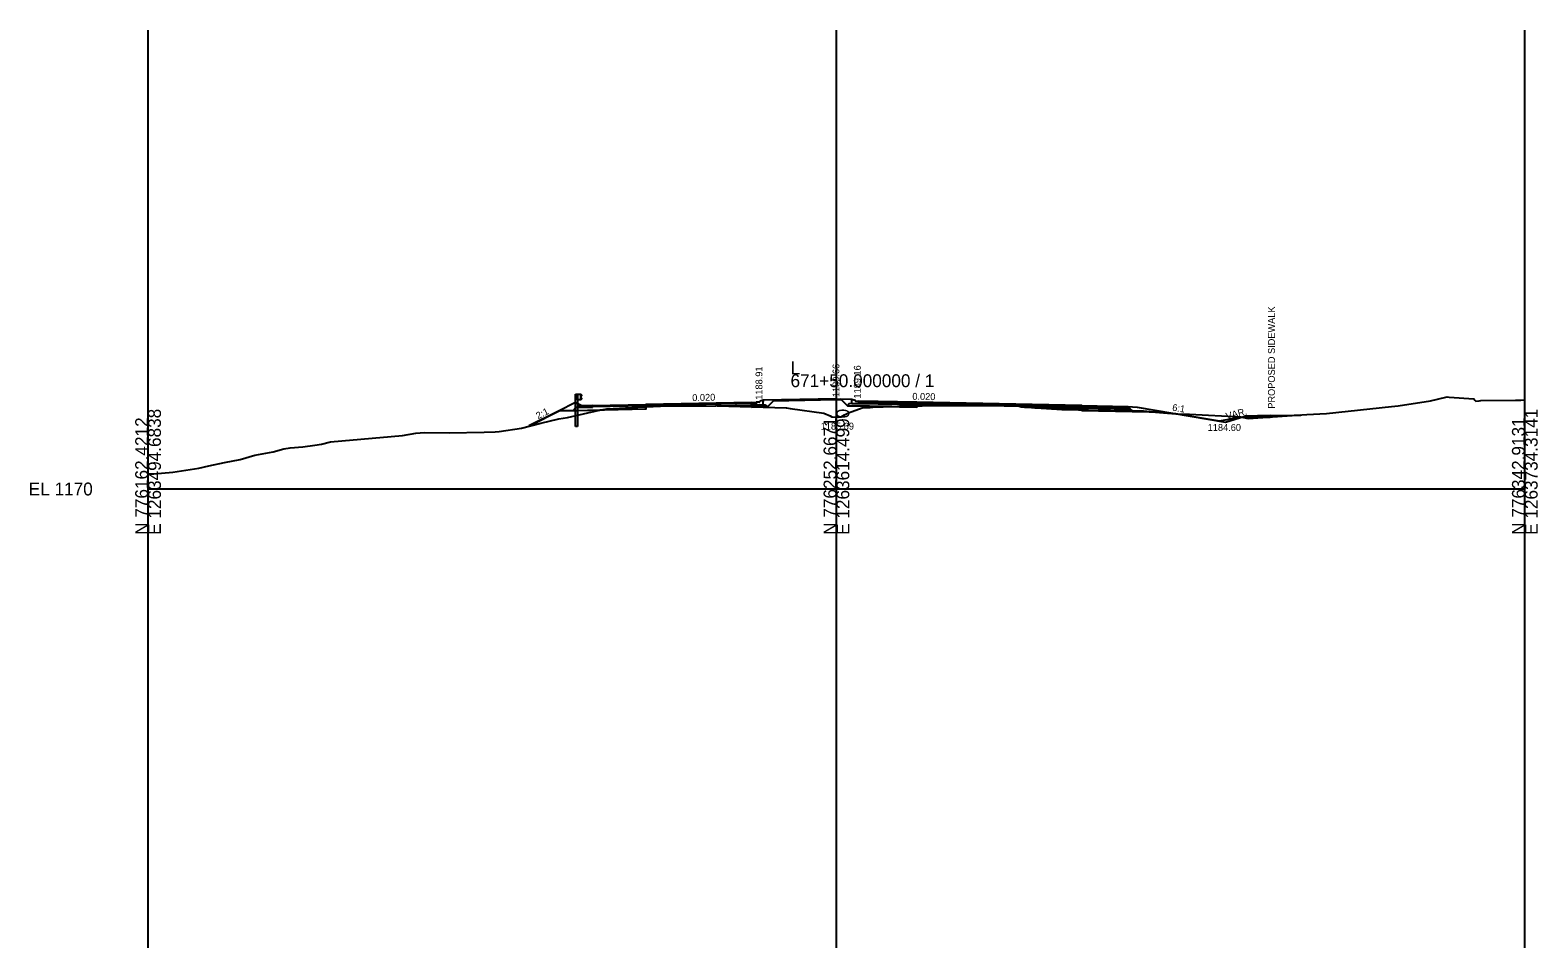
# Model space of a CAD drawing. Extents: x -41 to 1262860, y -100 to 777489.
# Drawn here: x -25.7 to 302.8, y 4085 to 4285 of the extents above; entities that cross this region are included whole.
import ezdxf

# ---------------------------------------------------------------- set-up
doc = ezdxf.new("R2010")
doc.units = 0
for name, color, linetype in [('Exist Cross Section Cell', 7, 'Continuous'), ('Exist XS Center Line Elevation Label', 7, 'Continuous'), ('Exist XS Ground Line', 7, 'Continuous'), ('Prop CMT Guardrail Graphics', 7, 'Continuous'), ('Prop CMT Pvmt Concrete', 7, 'Continuous'), ('Prop CMT Pvmt Course 1', 7, 'Continuous'), ('Prop CMT Pvmt Course 4', 7, 'Continuous'), ('Prop CMT Pvmt Surface', 7, 'Continuous'), ('Prop CMT Shld Paved Course 1', 7, 'Continuous'), ('Prop CMT Shld Paved Course 2', 7, 'Continuous'), ('Prop CMT Shld Paved Course 4', 7, 'Continuous'), ('Prop CMT Slope Grass', 7, 'Continuous'), ('Prop CMT Subgrade Earthwork', 7, 'Continuous'), ('Prop Conc Curb and Gutter', 7, 'Continuous'), ('Prop Conc Island Cover', 7, 'Continuous'), ('Prop XS Ditch Standard Text', 7, 'Continuous'), ('Prop XS Earthwork Shape', 7, 'Continuous'), ('Prop XS Elevation Labels', 7, 'Continuous'), ('Prop XS Exc Vertical Line 1', 7, 'Continuous'), ('Prop XS Exc Vertical Line 2', 7, 'Continuous'), ('Prop XS Exc Vertical Line 3', 7, 'Continuous'), ('Prop XS Finish Grade', 7, 'Continuous'), ('Prop XS Hydro Elevations', 7, 'Continuous'), ('Prop XS SE Text', 7, 'Continuous'), ('Prop XS Side Slope Text', 7, 'Continuous'), ('Scratch_Level_0', 7, 'Continuous'), ('Scratch_Level_1', 7, 'Continuous'), ('Scratch_Level_4', 7, 'Continuous'), ('Scratch_Level_6', 7, 'Continuous'), ('Typical Curb CELL', 7, 'Continuous')]:
    doc.layers.add(name, color=color, linetype=linetype)

msp = doc.modelspace()

# ---------------------------------------------------------------- linework, layer by layer
at = {"layer": 'Exist Cross Section Cell'}
for p, q in [((150, 4185), (150, 4210)), ((0, 4185), (150, 4185)), ((150, 4185), (300, 4185))]:
    msp.add_line(p, q, dxfattribs=at)
at = {"layer": 'Exist XS Ground Line'}
msp.add_lwpolyline([(0, 4188.19), (1.25, 4188.27), (5.42, 4188.68), (11.06, 4189.57), (13.24, 4190.03), (16.64, 4190.74), (20.1, 4191.4), (23.26, 4192.34), (27.27, 4193.11), (29.58, 4193.74), (30.93, 4193.95), (33.75, 4194.16), (36.34, 4194.53), (37.8, 4194.78), (39.72, 4195.25), (55.47, 4196.67), (58.32, 4197.15), (60.24, 4197.34), (65.58, 4197.24), (73.27, 4197.41), (75.61, 4197.46), (76.49, 4197.5), (81.36, 4198.29), (85.61, 4199.38), (89.52, 4200.26), (91.43, 4200.58), (98.34, 4202.15), (99.94, 4202.49), (102.73, 4202.62), (108, 4202.88), (108.47, 4202.9), (111.69, 4203.03), (123.74, 4203.16), (124.01, 4203.17), (124.04, 4203.16), (136.61, 4202.79), (139.05, 4202.67), (139.15, 4202.66), (139.9, 4202.56), (147.26, 4201.53), (148.6, 4200.91), (148.97, 4200.73), (150.46, 4200.68), (151.03, 4200.71), (151.77, 4201.19), (152.37, 4201.48), (152.63, 4201.61), (152.66, 4201.61), (155.62, 4202.66), (157.34, 4202.76), (157.93, 4202.8), (160.15, 4202.89), (165.51, 4203.1), (168.68, 4203.14), (177.04, 4203.22), (183.2, 4203.19), (189.79, 4203.03), (190.23, 4202.89), (192.49, 4202.74), (193.2, 4202.69), (194.62, 4202.62), (199.11, 4202.31), (200.56, 4202.3), (204.93, 4202.18), (214.62, 4202.07), (216.89, 4201.95), (221.25, 4201.61), (224.82, 4201.34), (226.93, 4201.29), (238.02, 4200.7), (239.72, 4200.34), (248.22, 4200.94), (252.49, 4201.2), (256.76, 4201.47), (270.96, 4202.98), (272.41, 4203.14), (279.43, 4204.22), (282.8, 4204.99), (283.1, 4205.06), (283.5, 4205.03), (288.86, 4204.62), (289.11, 4204.37), (289.36, 4204.12), (290.06, 4204.22), (290.44, 4204.27), (297.95, 4204.34), (299.11, 4204.37), (300, 4204.4)], dxfattribs=at)
at = {"layer": 'Prop CMT Guardrail Graphics'}
for p, q in [((93.11, 4205.64), (93.59, 4205.64)), ((93.11, 4203.14), (93.11, 4205.64)), ((93.59, 4204.46), (93.59, 4205.64)), ((93.59, 4205.64), (94.26, 4205.64)), ((93.59, 4205.64), (93.59, 4203.13)), ((94.26, 4205.64), (94.26, 4204.46)), ((94.26, 4205.56), (94.26, 4204.54)), ((94.36, 4205.54), (94.26, 4205.56)), ((94.27, 4205.1), (94.5, 4205.3)), ((94.5, 4205.44), (94.36, 4205.54)), ((94.5, 4205.3), (94.5, 4205.44)), ((93.11, 4198.64), (93.11, 4203.14)), ((94.26, 4204.46), (93.59, 4204.46)), ((93.59, 4203.13), (93.59, 4198.64)), ((94.26, 4204.54), (94.36, 4204.56)), ((94.27, 4205.01), (94.27, 4205.1)), ((94.5, 4204.81), (94.27, 4205.01)), ((94.36, 4204.56), (94.5, 4204.66)), ((94.5, 4204.66), (94.5, 4204.81)), ((93.59, 4198.64), (93.11, 4198.64))]:
    msp.add_line(p, q, dxfattribs=at)
at = {"layer": 'Prop CMT Pvmt Concrete'}
for p, q in [((239.5, 4200.89), (244.5, 4200.99)), ((239.5, 4200.89), (239.5, 4200.55)), ((239.5, 4200.55), (244.51, 4200.65)), ((244.5, 4200.99), (244.5, 4200.65))]:
    msp.add_line(p, q, dxfattribs=at)
at = {"layer": 'Prop CMT Pvmt Course 1'}
for p, q in [((131.5, 4203.62), (132.5, 4203.64)), ((132.5, 4203.64), (132.5, 4203.89)), ((154.86, 4204.15), (154.86, 4203.9)), ((167.5, 4203.64), (154.86, 4203.9))]:
    msp.add_line(p, q, dxfattribs=at)
for points in [[(108.5, 4203.16), (108.5, 4203.41), (108.5, 4203.41), (131.5, 4203.87), (131.5, 4203.62), (131.5, 4203.62), (108.5, 4203.16), (108.5, 4203.16), (108.5, 4203.16)], [(203.5, 4202.92), (203.5, 4203.17), (203.5, 4203.17), (167.5, 4203.89), (167.5, 4203.64), (167.5, 4203.64), (203.5, 4202.92), (203.5, 4202.92), (203.5, 4202.92)]]:
    msp.add_lwpolyline(points, dxfattribs=at)
at = {"layer": 'Prop CMT Pvmt Course 4'}
msp.add_line((108.5, 4202.37), (93.44, 4202.07), dxfattribs=at)
at = {"layer": 'Prop CMT Pvmt Surface'}
for p, q in [((96.82, 4203.18), (108.5, 4203.41)), ((131.5, 4203.87), (108.5, 4203.41)), ((131.5, 4203.87), (132.5, 4203.89)), ((167.5, 4203.89), (154.86, 4204.15)), ((203.5, 4203.17), (167.5, 4203.89)), ((203.5, 4203.17), (213.5, 4202.97))]:
    msp.add_line(p, q, dxfattribs=at)
at = {"layer": 'Prop CMT Shld Paved Course 1'}
for p, q in [((108.5, 4203.16), (96.82, 4202.93)), ((104.5, 4203.33), (104.5, 4203.33)), ((108.5, 4203.41), (108.5, 4203.16)), ((108.5, 4203.16), (108.5, 4203.16)), ((203.5, 4203.17), (203.5, 4202.92)), ((203.5, 4202.92), (203.5, 4202.92)), ((203.5, 4202.92), (213.76, 4202.72)), ((207.5, 4203.09), (207.5, 4203.09)), ((213.76, 4202.72), (213.5, 4202.97))]:
    msp.add_line(p, q, dxfattribs=at)
at = {"layer": 'Prop CMT Shld Paved Course 2'}
for p, q in [((103.9, 4202.74), (103.9, 4202.74)), ((103.9, 4202.74), (103.9, 4202.74)), ((103.9, 4202.74), (103.9, 4202.74)), ((103.9, 4202.74), (103.9, 4202.74)), ((111.69, 4203.23), (108.5, 4203.16)), ((108.5, 4203.16), (108.5, 4202.83)), ((108.5, 4203.16), (108.5, 4203.16)), ((108.5, 4203.16), (108.5, 4202.9)), ((108.5, 4202.9), (111.69, 4203.03)), ((108.5, 4202.9), (108.5, 4202.9)), ((108.5, 4202.9), (108.5, 4202.9)), ((108.5, 4202.83), (108.5, 4202.83)), ((123.74, 4203.47), (111.69, 4203.23)), ((111.69, 4203.23), (111.69, 4203.23)), ((111.69, 4203.23), (111.69, 4203.23)), ((111.69, 4203.03), (123.74, 4203.16)), ((111.69, 4203.03), (111.69, 4203.03)), ((111.69, 4203.03), (111.69, 4203.03)), ((124.01, 4203.47), (123.74, 4203.47)), ((123.74, 4203.47), (123.74, 4203.47)), ((123.74, 4203.16), (124.01, 4203.17)), ((123.74, 4203.16), (123.74, 4203.16)), ((124.04, 4203.47), (124.01, 4203.47)), ((124.01, 4203.17), (124.04, 4203.16)), ((131.5, 4203.62), (124.04, 4203.47)), ((124.04, 4203.47), (124.04, 4203.47)), ((124.04, 4203.16), (124.52, 4203.15)), ((124.52, 4203.15), (131.5, 4203.29)), ((124.52, 4203.15), (124.52, 4203.15)), ((124.52, 4203.15), (124.52, 4203.15)), ((131.5, 4203.29), (131.5, 4203.62)), ((131.5, 4203.62), (131.5, 4203.62)), ((131.5, 4203.29), (132.5, 4203.31)), ((131.5, 4203.29), (131.5, 4203.29)), ((131.5, 4203.29), (131.5, 4203.29)), ((132.5, 4203.64), (132.5, 4203.31)), ((154.86, 4203.56), (154.86, 4203.9)), ((167.5, 4203.31), (154.86, 4203.56)), ((168.68, 4203.62), (167.5, 4203.64)), ((167.5, 4203.64), (167.5, 4203.31)), ((167.5, 4203.31), (167.5, 4203.31)), ((167.5, 4203.31), (168.68, 4203.29)), ((177.04, 4203.45), (168.68, 4203.62)), ((168.68, 4203.62), (168.68, 4203.62)), ((168.68, 4203.29), (168.68, 4203.29)), ((168.68, 4203.29), (173.63, 4203.19)), ((173.63, 4203.19), (177.04, 4203.22)), ((173.63, 4203.19), (173.63, 4203.19)), ((173.63, 4203.19), (173.63, 4203.19)), ((183.2, 4203.33), (177.04, 4203.45)), ((177.04, 4203.45), (177.04, 4203.45)), ((177.04, 4203.22), (183.2, 4203.19)), ((189.79, 4203.2), (183.2, 4203.33)), ((183.2, 4203.33), (183.2, 4203.33)), ((183.2, 4203.19), (183.2, 4203.19)), ((183.2, 4203.19), (189.79, 4203.03)), ((190.23, 4203.19), (189.79, 4203.2)), ((189.79, 4203.2), (189.79, 4203.2)), ((189.79, 4203.2), (189.79, 4203.2)), ((189.79, 4203.2), (189.79, 4203.2)), ((189.79, 4203.03), (189.79, 4203.03)), ((189.79, 4203.03), (189.79, 4203.03)), ((189.79, 4203.03), (189.79, 4203.03)), ((189.79, 4203.03), (190.23, 4202.89)), ((192.49, 4203.14), (190.23, 4203.19)), ((190.23, 4203.19), (190.23, 4203.19)), ((190.23, 4202.89), (191, 4202.84)), ((191, 4202.84), (191, 4202.84)), ((191, 4202.84), (192.49, 4202.81)), ((193.2, 4203.13), (192.49, 4203.14)), ((192.49, 4202.81), (192.49, 4202.81)), ((192.49, 4202.81), (193.2, 4202.8)), ((194.62, 4203.1), (193.2, 4203.13)), ((193.2, 4203.13), (193.2, 4203.13)), ((193.2, 4202.8), (193.2, 4202.8)), ((193.2, 4202.8), (194.62, 4202.77)), ((199.11, 4203.01), (194.62, 4203.1)), ((194.62, 4203.1), (194.62, 4203.1)), ((194.62, 4202.77), (194.62, 4202.77)), ((194.62, 4202.77), (199.11, 4202.68)), ((200.56, 4202.98), (199.11, 4203.01)), ((199.11, 4203.01), (199.11, 4203.01)), ((199.11, 4202.68), (199.11, 4202.68)), ((199.11, 4202.68), (200.56, 4202.65)), ((203.5, 4202.92), (200.56, 4202.98)), ((200.56, 4202.98), (200.56, 4202.98)), ((200.56, 4202.65), (200.56, 4202.65)), ((200.56, 4202.65), (203.5, 4202.59)), ((203.5, 4202.92), (203.5, 4202.59)), ((203.5, 4202.59), (203.5, 4202.92)), ((203.5, 4202.59), (203.5, 4202.59)), ((203.5, 4202.59), (214.1, 4202.38)), ((203.5, 4202.59), (203.5, 4202.59)), ((214.1, 4202.38), (213.76, 4202.72))]:
    msp.add_line(p, q, dxfattribs=at)
at = {"layer": 'Prop CMT Shld Paved Course 4'}
for p, q in [((92.55, 4202.05), (93.29, 4202.8)), ((93.29, 4202.8), (93.8, 4202.8)), ((103.9, 4202.74), (103.9, 4202.74)), ((103.9, 4202.74), (103.9, 4202.74)), ((108.5, 4202.83), (108.5, 4202.37)), ((124.52, 4203.15), (131.5, 4202.94)), ((131.5, 4202.83), (131.5, 4203.29)), ((131.5, 4202.83), (134.95, 4202.9)), ((132.5, 4203.31), (134.5, 4203.35)), ((134.5, 4203.35), (134.95, 4202.9)), ((152.86, 4203.6), (152.41, 4203.15)), ((167.5, 4202.85), (152.41, 4203.15)), ((154.86, 4203.56), (152.86, 4203.6)), ((167.5, 4202.85), (167.5, 4203.31)), ((168.68, 4203.14), (167.5, 4203.13)), ((173.63, 4203.19), (168.68, 4203.14)), ((192.49, 4202.74), (191, 4202.84)), ((193.2, 4202.69), (192.49, 4202.74)), ((194.62, 4202.62), (193.2, 4202.69)), ((199.11, 4202.31), (194.62, 4202.62)), ((200.56, 4202.3), (199.11, 4202.31)), ((200.56, 4202.3), (203.5, 4202.22)), ((203.5, 4202.59), (203.5, 4202.13)), ((203.5, 4202.13), (214.56, 4201.91)), ((214.56, 4201.91), (214.1, 4202.38))]:
    msp.add_line(p, q, dxfattribs=at)
at = {"layer": 'Prop CMT Slope Grass'}
for q in [(89.44, 4201.99), (93.8, 4203.48)]:
    msp.add_line((93.11, 4203.82), q, dxfattribs=at)
at = {"layer": 'Prop CMT Subgrade Earthwork'}
for p, q in [((108.5, 4202.37), (89.44, 4201.99)), ((108.5, 4202.37), (108.5, 4202.9)), ((131.5, 4202.83), (131.5, 4202.94)), ((134.95, 4202.9), (131.5, 4202.83)), ((134.95, 4202.9), (136.44, 4204.39)), ((152.41, 4203.15), (150.92, 4204.64)), ((152.41, 4203.15), (167.5, 4202.85)), ((167.5, 4202.85), (167.5, 4203.13)), ((203.5, 4202.22), (203.5, 4202.13)), ((203.5, 4202.13), (221.78, 4201.77))]:
    msp.add_line(p, q, dxfattribs=at)
at = {"layer": 'Prop Conc Curb and Gutter'}
for p, q in [((133.19, 4203.91), (132.5, 4203.89)), ((132.5, 4203.89), (132.5, 4203.31)), ((132.5, 4203.31), (134, 4203.34)), ((133.25, 4203.99), (133.25, 4203.97)), ((134, 4204.34), (133.35, 4204.12)), ((134, 4203.34), (134, 4204.34)), ((134, 4203.34), (134, 4203.34)), ((153.36, 4204.59), (154.01, 4204.38)), ((153.36, 4203.59), (153.36, 4204.59)), ((154.86, 4203.56), (153.36, 4203.59)), ((154.11, 4204.24), (154.11, 4204.22)), ((154.17, 4204.16), (154.86, 4204.15)), ((154.86, 4203.56), (154.86, 4204.15))]:
    msp.add_line(p, q, dxfattribs=at)
for centre, radius, start, end in [((133.19, 4203.97), 0.0625, 271.1458, 360), ((133.4, 4203.99), 0.146, 108.435, 180), ((153.96, 4204.24), 0.146, 0, 71.565), ((154.17, 4204.22), 0.0625, 180, 268.8542)]:
    msp.add_arc(centre, radius, start, end, dxfattribs=at)
at = {"layer": 'Prop Conc Island Cover'}
for p, q in [((150, 4204.66), (134, 4204.34)), ((134, 4204.08), (134, 4204.08)), ((150, 4204.66), (153.36, 4204.59))]:
    msp.add_line(p, q, dxfattribs=at)
at = {"layer": 'Prop XS Earthwork Shape'}
for points in [[(91.43, 4200.58), (98.34, 4202.15), (98.43, 4202.17), (93.44, 4202.07), (89.7, 4202), (83.28, 4198.78), (85.61, 4199.38), (89.52, 4200.26)], [(108.47, 4202.9), (108.5, 4202.9), (108.5, 4202.37), (98.43, 4202.17), (99.94, 4202.49), (102.73, 4202.62), (108, 4202.88)], [(131.5, 4202.83), (131.5, 4202.94), (133.71, 4202.88)], [(151.77, 4201.19), (152.37, 4201.48), (152.63, 4201.61), (152.66, 4201.61), (155.62, 4202.66), (157.34, 4202.76), (157.93, 4202.8), (160.15, 4202.89), (162.04, 4202.96), (152.41, 4203.15), (151.18, 4204.39), (150, 4204.41), (136.18, 4204.13), (134.95, 4202.9), (133.71, 4202.88), (136.61, 4202.79), (139.05, 4202.67), (139.15, 4202.66), (139.9, 4202.56), (147.26, 4201.53), (148.6, 4200.91), (148.97, 4200.73), (150.46, 4200.68), (151.03, 4200.71)], [(165.51, 4203.1), (167.5, 4203.13), (167.5, 4202.85), (162.04, 4202.96)], [(214.4, 4202.07), (214.56, 4201.91), (203.5, 4202.13), (203.5, 4202.22), (204.93, 4202.18)], [(214.4, 4202.07), (214.56, 4201.91), (218.38, 4201.83), (216.89, 4201.95), (214.62, 4202.07)], [(218.38, 4201.83), (221.78, 4201.77), (223.93, 4201.41), (221.25, 4201.61)], [(224.82, 4201.34), (226.93, 4201.29), (238.02, 4200.7), (238.21, 4200.66), (233.5, 4199.81), (223.93, 4201.41)], [(238.21, 4200.66), (239.5, 4200.89), (244.5, 4200.99), (251.16, 4201.12), (248.22, 4200.94), (239.72, 4200.34)]]:
    msp.add_lwpolyline(points, close=True, dxfattribs=at)
at = {"layer": 'Prop XS Exc Vertical Line 1'}
msp.add_line((0, 4085), (0, 4285), dxfattribs=at)
at = {"layer": 'Prop XS Exc Vertical Line 2'}
msp.add_line((150, 4085), (150, 4285), dxfattribs=at)
at = {"layer": 'Prop XS Exc Vertical Line 3'}
msp.add_line((300, 4085), (300, 4285), dxfattribs=at)
at = {"layer": 'Prop XS Finish Grade'}
for p, q in [((89.44, 4201.99), (82.97, 4198.76)), ((213.5, 4202.97), (215.5, 4202.81)), ((213.5, 4202.97), (214.56, 4201.91)), ((215.5, 4202.81), (234.76, 4199.6)), ((234.76, 4199.6), (239, 4200.88)), ((244.5, 4200.99), (239, 4200.88)), ((244.5, 4200.99), (251.16, 4201.12))]:
    msp.add_line(p, q, dxfattribs=at)
at = {"layer": 'Scratch_Level_0'}
for p, q in [((134, 4204.34), (134, 4204.09)), ((153.36, 4204.59), (153.36, 4204.34))]:
    msp.add_line(p, q, dxfattribs=at)
at = {"layer": 'Scratch_Level_1'}
msp.add_line((239.5, 4200.89), (244.5, 4200.99), dxfattribs=at)
at = {"layer": 'Scratch_Level_4'}
msp.add_line((300, 4085), (300, 4285), dxfattribs=at)
at = {"layer": 'Scratch_Level_6'}
msp.add_line((0, 4085), (0, 4285), dxfattribs=at)
at = {"layer": 'Typical Curb CELL'}
for p, q in [((93.8, 4202.8), (93.81, 4203.47)), ((93.8, 4202.8), (96.82, 4202.77)), ((94.49, 4203.12), (93.81, 4203.47)), ((93.84, 4203.09), (93.99, 4203.14)), ((93.98, 4203.05), (93.84, 4203.09)), ((93.99, 4203.14), (93.98, 4203.05)), ((94.51, 4203), (94.4, 4202.93)), ((94.4, 4202.93), (94.57, 4202.89)), ((96.81, 4203.18), (94.49, 4203.12)), ((94.57, 4202.89), (94.51, 4203)), ((95.25, 4203.05), (95.21, 4202.94)), ((95.21, 4202.94), (95.33, 4202.93)), ((95.33, 4202.93), (95.25, 4203.05)), ((95.76, 4202.99), (95.65, 4202.92)), ((95.65, 4202.92), (95.82, 4202.88)), ((95.82, 4202.88), (95.76, 4202.99)), ((96.5, 4203.04), (96.46, 4202.93)), ((96.46, 4202.93), (96.58, 4202.92)), ((96.58, 4202.92), (96.5, 4203.04)), ((96.82, 4203.18), (96.82, 4203.18)), ((96.82, 4202.77), (96.82, 4203.17))]:
    msp.add_line(p, q, dxfattribs=at)
for centre in [(93.87, 4203.18), (93.96, 4202.9), (94.08, 4202.95), (94.34, 4202.98), (94.36, 4202.93), (94.53, 4202.84), (94.56, 4202.94), (94.76, 4202.9), (94.8, 4203.02), (94.93, 4202.99), (94.96, 4202.86), (95.02, 4202.89), (95.21, 4202.89), (95.33, 4202.94), (95.43, 4202.93), (95.52, 4202.88), (95.58, 4203.03), (95.59, 4202.97), (95.61, 4202.92), (95.81, 4202.93), (96.01, 4202.89), (96.05, 4203.01), (96.1, 4202.97), (96.18, 4202.98), (96.21, 4202.85), (96.27, 4202.88), (96.33, 4203.06), (96.7, 4203.13), (96.73, 4203.01)]:
    msp.add_circle(centre, 0.00802, dxfattribs=at)
msp.add_arc((96.81, 4203.17), 0.0104, 359.4338, 91.4818, dxfattribs=at)

# ---------------------------------------------------------------- texts
at = {"layer": 'Exist Cross Section Cell'}
for s, p in [('L', (140, 4210)), ('671+50.000000 / 1', (140, 4207.2)), ('EL 1170', (-26, 4183.6))]:
    msp.add_text(s, height=2.8, dxfattribs=at).set_placement(p)
for s, p in [('E 1263494.6838', (2.8, 4175)), ('E 1263614.4990', (152.8, 4175)), ('E 1263734.3141', (302.8, 4175)), ('N 776162.4212', (0, 4175)), ('N 776252.6671', (150, 4175)), ('N 776342.9131', (300, 4175))]:
    msp.add_text(s, height=2.8, rotation=90, dxfattribs=at).set_placement(p)
at = {"layer": 'Exist XS Center Line Elevation Label'}
msp.add_text('1185.69', height=1.5, dxfattribs=at).set_placement((146.57, 4197.94))
at = {"layer": 'Prop XS Ditch Standard Text'}
msp.add_text('1184.60', height=1.5, dxfattribs=at).set_placement((230.9, 4197.66))
at = {"layer": 'Prop XS Elevation Labels'}
for s, p in [('1189.16', (155.3, 4204.71)), ('1188.91', (133.87, 4204.45))]:
    msp.add_text(s, height=1.5, rotation=90, dxfattribs=at).set_placement(p)
at = {"layer": 'Prop XS Hydro Elevations'}
for s, p in [('PROPOSED SIDEWALK', (245.55, 4202.5)), ('1189.66', (150.65, 4205.03))]:
    msp.add_text(s, height=1.5, rotation=90, dxfattribs=at).set_placement(p)
at = {"layer": 'Prop XS SE Text'}
for rotation, p in [(1.1458, (118.59, 4204.16)), (358.8542, (166.53, 4204.46))]:
    msp.add_text('0.020', height=1.5, rotation=rotation, dxfattribs=at).set_placement(p)
at = {"layer": 'Prop XS Side Slope Text'}
for s, rotation, p in [('2:1', 26.5651, (84.98, 4200.18)), ('6:1', 350.5377, (223.09, 4202.09)), ('VAR.', 14.2871, (235.06, 4200.11))]:
    msp.add_text(s, height=1.5, rotation=rotation, dxfattribs=at).set_placement(p)

doc.saveas('drawing.dxf')
